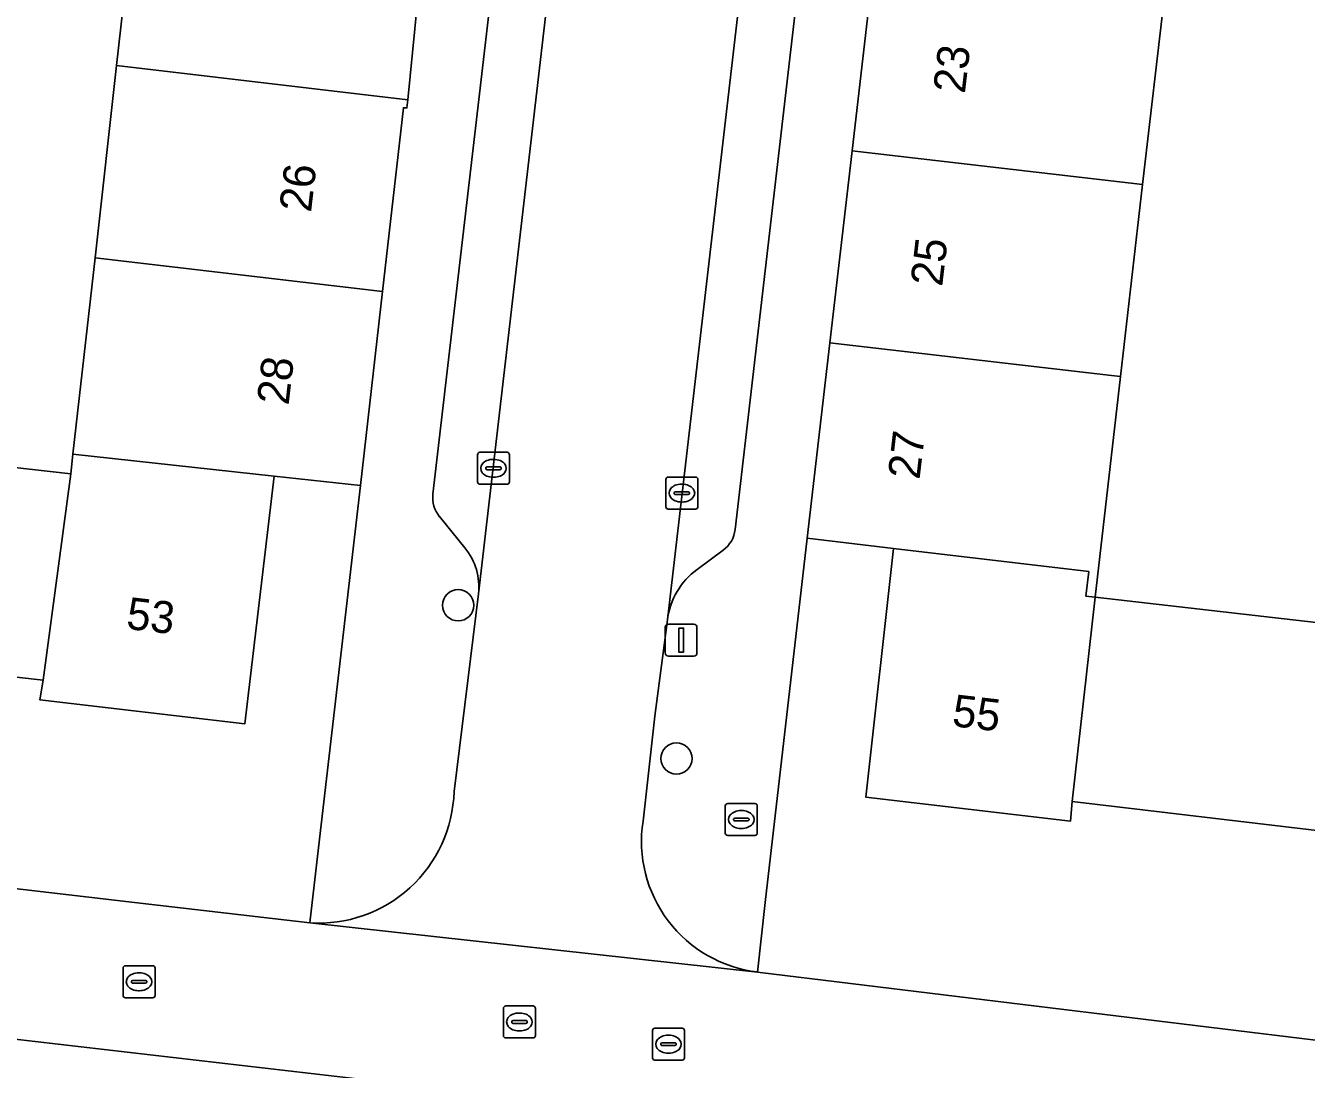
# Model space of a CAD drawing. Extents: x 161241 to 161758, y 384138 to 384885.
# Drawn here: x 161433.37 to 161473.44, y 384494.77 to 384527.43 of the extents above; entities that cross this region are included whole.
import ezdxf

# ---------------------------------------------------------------- set-up
doc = ezdxf.new("R2010")
doc.units = 0
for name, color, linetype in [('IMGEO_Boom', 7, 'Continuous'), ('IMGEO_Brandkraan', 7, 'Continuous'), ('IMGEO_Erf', 7, 'Continuous'), ('IMGEO_Kolk', 7, 'Continuous'), ('IMGEO_Lichtmast', 7, 'Continuous'), ('IMGEO_Pand', 7, 'Continuous'), ('IMGEO_Pand_nummerreeks', 7, 'Continuous'), ('IMGEO_Parkeervlak_open', 7, 'Continuous'), ('IMGEO_Rijbaan_lokaal_open', 7, 'Continuous'), ('IMGEO_Rioolput', 7, 'Continuous'), ('IMGEO_Voetpad_open', 7, 'Continuous')]:
    doc.layers.add(name, color=color, linetype=linetype)

msp = doc.modelspace()

# ---------------------------------------------------------------- linework, layer by layer
at = {"layer": 'IMGEO_Boom'}
for centre in [(161446.901, 384509.294), (161453.731, 384504.499)]:
    msp.add_circle(centre, 0.489, dxfattribs=at)
at = {"layer": 'IMGEO_Brandkraan'}
for p, q in [((161455.259, 384502.166), (161455.259, 384503.018)), ((161455.334, 384503.092), (161456.186, 384503.092)), ((161455.747, 384502.872), (161455.772, 384502.872)), ((161456.26, 384503.018), (161456.26, 384502.166)), ((161455.518, 384502.586), (161455.518, 384502.598)), ((161455.956, 384502.549), (161455.558, 384502.549)), ((161455.561, 384502.635), (161455.959, 384502.635)), ((161456.002, 384502.598), (161456.002, 384502.586)), ((161456.186, 384502.092), (161455.334, 384502.092)), ((161455.77, 384502.312), (161455.745, 384502.312))]:
    msp.add_line(p, q, dxfattribs=at)
for points in [[(161455.259, 384502.166), (161455.259, 384503.018)], [(161455.334, 384503.092), (161456.186, 384503.092)], [(161456.26, 384503.018), (161456.26, 384502.166)], [(161456.186, 384502.092), (161455.334, 384502.092)]]:
    msp.add_lwpolyline(points, dxfattribs=at)
for centre, radius, start, end in [((161455.336, 384503.016), 0.0765, 91.552, 178.448), ((161455.336, 384503.016), 0.0765, 91.552, 178.448), ((161456.184, 384503.016), 0.0765, 1.552, 88.448), ((161456.184, 384503.016), 0.0765, 1.552, 88.448), ((161455.558, 384502.595), 0.0403, 85.8775, 175.7526), ((161455.555, 384502.585), 0.0366, 178.938, 274.7102), ((161455.959, 384502.592), 0.043, 264.8664, 352.4533), ((161455.963, 384502.597), 0.0386, 1.7309, 96.639), ((161455.336, 384502.168), 0.0765, 181.552, 268.448), ((161455.336, 384502.168), 0.0765, 181.552, 268.448), ((161456.184, 384502.168), 0.0765, 271.552, 358.448), ((161456.184, 384502.168), 0.0765, 271.552, 358.448)]:
    msp.add_arc(centre, radius, start, end, dxfattribs=at)
for centre, major_axis, ratio, start_param, end_param in [((161455.746, 384502.592), (-0.387, 0.002), 0.722429, 4.712389, 7.853982), ((161455.771, 384502.592), (-0.39, 0.002), 0.717154, 1.570796, 4.712389)]:
    msp.add_ellipse(centre, major_axis=major_axis, ratio=ratio, start_param=start_param, end_param=end_param, dxfattribs=at)
at = {"layer": 'IMGEO_Erf'}
for points in [[(161363.697, 384528.581), (161363.009, 384522.448), (161362.9, 384521.481), (161371.708, 384520.492), (161371.808, 384521.386), (161377.931, 384520.699), (161383.926, 384520.026), (161389.92, 384519.353), (161395.914, 384518.68), (161401.908, 384518.007), (161407.903, 384517.334), (161413.897, 384516.661), (161419.892, 384515.989), (161426.097, 384515.292), (161425.996, 384514.397), (161434.78, 384513.411), (161434.849, 384514.022), (161435.538, 384520.166), (161436.213, 384526.177), (161436.887, 384532.189)], [(161469.007, 384528.458), (161468.317, 384522.455), (161467.626, 384516.45), (161466.833, 384509.551), (161475.383, 384508.568)], [(161430.603, 384500.72), (161436.769, 384500), (161442.259, 384499.359), (161442.333, 384500), (161443.841, 384513.042), (161441.142, 384513.335), (161440.226, 384505.59), (161433.816, 384506.335), (161433.916, 384506.947), (161425.107, 384507.945)], [(161474.911, 384502.113), (161466.108, 384503.152), (161466.063, 384502.544), (161459.651, 384503.294), (161460.525, 384511.068), (161457.818, 384511.391), (161456.511, 384500), (161456.261, 384497.821), (161473.721, 384495.685)]]:
    msp.add_lwpolyline(points, dxfattribs=at)
at = {"layer": 'IMGEO_Kolk'}
for p, q in [((161447.505, 384513.154), (161447.505, 384514.006)), ((161447.58, 384514.08), (161448.432, 384514.08)), ((161448.506, 384514.006), (161448.506, 384513.154)), ((161447.807, 384513.623), (161448.205, 384513.623)), ((161447.993, 384513.86), (161448.018, 384513.86)), ((161447.764, 384513.574), (161447.764, 384513.586)), ((161448.202, 384513.537), (161447.804, 384513.537)), ((161448.016, 384513.3), (161447.991, 384513.3)), ((161448.248, 384513.586), (161448.248, 384513.574)), ((161453.399, 384512.378), (161453.399, 384513.23)), ((161453.474, 384513.304), (161454.326, 384513.304)), ((161454.4, 384513.23), (161454.4, 384512.378)), ((161448.432, 384513.08), (161447.58, 384513.08)), ((161453.658, 384512.798), (161453.658, 384512.81)), ((161453.701, 384512.847), (161454.099, 384512.847)), ((161453.887, 384513.084), (161453.912, 384513.084)), ((161454.142, 384512.81), (161454.142, 384512.798)), ((161454.096, 384512.761), (161453.698, 384512.761)), ((161453.91, 384512.524), (161453.885, 384512.524)), ((161454.326, 384512.304), (161453.474, 384512.304)), ((161436.491, 384498.015), (161437.343, 384498.015)), ((161436.416, 384497.089), (161436.416, 384497.941)), ((161436.904, 384497.795), (161436.929, 384497.795)), ((161437.417, 384497.941), (161437.417, 384497.089)), ((161436.675, 384497.509), (161436.675, 384497.521)), ((161437.113, 384497.472), (161436.715, 384497.472)), ((161436.718, 384497.558), (161437.116, 384497.558)), ((161436.927, 384497.235), (161436.902, 384497.235)), ((161437.159, 384497.521), (161437.159, 384497.509)), ((161437.343, 384497.015), (161436.491, 384497.015)), ((161452.98, 384495.137), (161452.98, 384495.989)), ((161453.055, 384496.063), (161453.907, 384496.063)), ((161453.981, 384495.989), (161453.981, 384495.137)), ((161453.239, 384495.557), (161453.239, 384495.569)), ((161453.282, 384495.606), (161453.68, 384495.606)), ((161453.468, 384495.843), (161453.493, 384495.843)), ((161453.723, 384495.569), (161453.723, 384495.557)), ((161453.677, 384495.52), (161453.279, 384495.52)), ((161453.491, 384495.283), (161453.466, 384495.283)), ((161453.907, 384495.063), (161453.055, 384495.063))]:
    msp.add_line(p, q, dxfattribs=at)
for points in [[(161447.505, 384513.154), (161447.505, 384514.006)], [(161447.58, 384514.08), (161448.432, 384514.08)], [(161448.506, 384514.006), (161448.506, 384513.154)], [(161453.399, 384512.378), (161453.399, 384513.23)], [(161453.474, 384513.304), (161454.326, 384513.304)], [(161454.4, 384513.23), (161454.4, 384512.378)], [(161448.432, 384513.08), (161447.58, 384513.08)], [(161454.326, 384512.304), (161453.474, 384512.304)], [(161436.491, 384498.015), (161437.343, 384498.015)], [(161436.416, 384497.089), (161436.416, 384497.941)], [(161437.417, 384497.941), (161437.417, 384497.089)], [(161437.343, 384497.015), (161436.491, 384497.015)], [(161452.98, 384495.137), (161452.98, 384495.989)], [(161453.055, 384496.063), (161453.907, 384496.063)], [(161453.981, 384495.989), (161453.981, 384495.137)], [(161453.907, 384495.063), (161453.055, 384495.063)]]:
    msp.add_lwpolyline(points, dxfattribs=at)
for centre, radius, start, end in [((161447.582, 384514.004), 0.0765, 91.552, 178.448), ((161447.582, 384514.004), 0.0765, 91.552, 178.448), ((161448.43, 384514.004), 0.0765, 1.552, 88.448), ((161448.43, 384514.004), 0.0765, 1.552, 88.448), ((161447.804, 384513.583), 0.0403, 85.8775, 175.7526), ((161448.209, 384513.585), 0.0386, 1.7309, 96.639), ((161447.801, 384513.573), 0.0366, 178.938, 274.7102), ((161448.205, 384513.58), 0.043, 264.8664, 352.4533), ((161453.476, 384513.228), 0.0765, 91.552, 178.448), ((161453.476, 384513.228), 0.0765, 91.552, 178.448), ((161454.324, 384513.228), 0.0765, 1.552, 88.448), ((161454.324, 384513.228), 0.0765, 1.552, 88.448), ((161447.582, 384513.156), 0.0765, 181.552, 268.448), ((161447.582, 384513.156), 0.0765, 181.552, 268.448), ((161448.43, 384513.156), 0.0765, 271.552, 358.448), ((161448.43, 384513.156), 0.0765, 271.552, 358.448), ((161453.698, 384512.807), 0.0403, 85.8775, 175.7526), ((161453.695, 384512.797), 0.0366, 178.938, 274.7102), ((161454.099, 384512.804), 0.043, 264.8664, 352.4533), ((161454.103, 384512.809), 0.0386, 1.7309, 96.639), ((161453.476, 384512.38), 0.0765, 181.552, 268.448), ((161453.476, 384512.38), 0.0765, 181.552, 268.448), ((161454.324, 384512.38), 0.0765, 271.552, 358.448), ((161454.324, 384512.38), 0.0765, 271.552, 358.448), ((161436.493, 384497.939), 0.0765, 91.552, 178.448), ((161436.493, 384497.939), 0.0765, 91.552, 178.448), ((161437.341, 384497.939), 0.0765, 1.552, 88.448), ((161437.341, 384497.939), 0.0765, 1.552, 88.448), ((161436.715, 384497.518), 0.0403, 85.8775, 175.7526), ((161436.712, 384497.508), 0.0366, 178.938, 274.7102), ((161437.116, 384497.515), 0.043, 264.8664, 352.4533), ((161437.12, 384497.52), 0.0386, 1.7309, 96.639), ((161436.493, 384497.091), 0.0765, 181.552, 268.448), ((161436.493, 384497.091), 0.0765, 181.552, 268.448), ((161437.341, 384497.091), 0.0765, 271.552, 358.448), ((161437.341, 384497.091), 0.0765, 271.552, 358.448), ((161453.057, 384495.987), 0.0765, 91.552, 178.448), ((161453.057, 384495.987), 0.0765, 91.552, 178.448), ((161453.905, 384495.987), 0.0765, 1.552, 88.448), ((161453.905, 384495.987), 0.0765, 1.552, 88.448), ((161453.279, 384495.566), 0.0403, 85.8775, 175.7526), ((161453.276, 384495.556), 0.0366, 178.938, 274.7102), ((161453.68, 384495.563), 0.043, 264.8664, 352.4533), ((161453.684, 384495.568), 0.0386, 1.7309, 96.639), ((161453.057, 384495.139), 0.0765, 181.552, 268.448), ((161453.057, 384495.139), 0.0765, 181.552, 268.448), ((161453.905, 384495.139), 0.0765, 271.552, 358.448), ((161453.905, 384495.139), 0.0765, 271.552, 358.448)]:
    msp.add_arc(centre, radius, start, end, dxfattribs=at)
for centre, major_axis, ratio, start_param, end_param in [((161447.992, 384513.58), (-0.387, 0.002), 0.722429, 4.712389, 7.853982), ((161448.017, 384513.58), (-0.39, 0.002), 0.717154, 1.570796, 4.712389), ((161453.886, 384512.804), (-0.387, 0.002), 0.722429, 4.712389, 7.853982), ((161453.911, 384512.804), (-0.39, 0.002), 0.717154, 1.570796, 4.712389), ((161436.903, 384497.515), (-0.387, 0.002), 0.722429, 4.712389, 7.853982), ((161436.928, 384497.515), (-0.39, 0.002), 0.717154, 1.570796, 4.712389), ((161453.467, 384495.563), (-0.387, 0.002), 0.722429, 4.712389, 7.853982), ((161453.492, 384495.563), (-0.39, 0.002), 0.717154, 1.570796, 4.712389)]:
    msp.add_ellipse(centre, major_axis=major_axis, ratio=ratio, start_param=start_param, end_param=end_param, dxfattribs=at)
at = {"layer": 'IMGEO_Lichtmast'}
for p, q in [((161453.382, 384507.806), (161453.382, 384508.606)), ((161453.382, 384508.606), (161453.382, 384507.806)), ((161453.482, 384508.706), (161454.272, 384508.706)), ((161454.272, 384508.706), (161453.482, 384508.706)), ((161454.372, 384508.606), (161454.372, 384507.806)), ((161454.372, 384507.806), (161454.372, 384508.606)), ((161454.272, 384507.706), (161453.482, 384507.706)), ((161453.482, 384507.706), (161454.272, 384507.706))]:
    msp.add_line(p, q, dxfattribs=at)
msp.add_lwpolyline([(161453.802, 384508.581), (161453.952, 384508.581), (161453.952, 384507.831), (161453.802, 384507.831), (161453.802, 384508.581)], dxfattribs=at)
for centre, start, end in [((161453.482, 384508.606), 90, 180), ((161453.482, 384508.606), 90, 180), ((161454.272, 384508.606), 0, 90), ((161454.272, 384508.606), 360, 90), ((161453.482, 384507.806), 180, 270), ((161453.482, 384507.806), 180, 270), ((161454.272, 384507.806), 270, 0), ((161454.272, 384507.806), 270, 0)]:
    msp.add_arc(centre, 0.1, start, end, dxfattribs=at)
at = {"layer": 'IMGEO_Pand'}
for points in [[(161445.896, 384530.942), (161446.196, 384530.954), (161446.21, 384531.096), (161436.887, 384532.189), (161436.213, 384526.177), (161445.323, 384525.109)], [(161459.642, 384529.306), (161459.894, 384529.296), (161459.223, 384523.508), (161468.317, 384522.455), (161469.007, 384528.458), (161468.733, 384528.49), (161459.667, 384529.54)], [(161445.19, 384524.858), (161445.298, 384524.857), (161445.323, 384525.109), (161436.213, 384526.177), (161435.538, 384520.166), (161444.534, 384519.111)], [(161458.527, 384517.504), (161467.343, 384516.483), (161467.626, 384516.45), (161468.317, 384522.455), (161459.223, 384523.508)], [(161444.534, 384519.111), (161435.538, 384520.166), (161434.849, 384514.022), (161441.142, 384513.335), (161443.841, 384513.042)], [(161457.818, 384511.391), (161460.525, 384511.068), (161466.632, 384510.347), (161466.543, 384509.584), (161466.833, 384509.551), (161467.626, 384516.45), (161467.343, 384516.483), (161458.527, 384517.504)], [(161418.823, 384506.88), (161424.878, 384506.193), (161425.107, 384507.945), (161433.916, 384506.947), (161434.78, 384513.411), (161425.996, 384514.397), (161426.097, 384515.292), (161419.892, 384515.989)], [(161434.849, 384514.022), (161434.78, 384513.411), (161433.916, 384506.947), (161433.816, 384506.335), (161440.226, 384505.59), (161441.142, 384513.335)], [(161466.543, 384509.584), (161466.632, 384510.347), (161460.525, 384511.068), (161459.651, 384503.294), (161466.063, 384502.544), (161466.108, 384503.152), (161466.833, 384509.551)], [(161475.383, 384508.568), (161466.833, 384509.551), (161466.108, 384503.152), (161474.911, 384502.113), (161475.672, 384508.413), (161475.37, 384508.45)]]:
    msp.add_lwpolyline(points, close=True, dxfattribs=at)
at = {"layer": 'IMGEO_Parkeervlak_open'}
for points in [[(161447.539, 384509.648), (161451.359, 384542.556), (161451.881, 384547.095), (161450.128, 384547.299), (161449.597, 384542.748), (161446.111, 384512.773)], [(161455.567, 384511.666), (161459.568, 384546.2), (161457.814, 384546.404), (161453.447, 384508.842)], [(161446.316, 384512.067), (161447.113, 384511.087)], [(161454.376, 384510.418), (161455.191, 384511.018)]]:
    msp.add_lwpolyline(points, dxfattribs=at)
for centre, radius, start, end in [((161447.048, 384512.662), 0.944, 173.271, 219.1122), ((161454.644, 384511.769), 0.929, 306.0898, 353.6616), ((161445.6, 384509.857), 1.95, 353.861, 39.1206), ((161455.754, 384508.544), 2.326, 126.3295, 172.6346)]:
    msp.add_arc(centre, radius, start, end, dxfattribs=at)
at = {"layer": 'IMGEO_Rijbaan_lokaal_open'}
for points in [[(161452.684, 384502.539), (161453.058, 384505.828), (161453.447, 384508.842), (161457.814, 384546.404), (161451.881, 384547.095), (161451.359, 384542.556), (161447.539, 384509.648), (161446.771, 384503.468)], [(161513.174, 384491.028), (161506.677, 384491.817), (161500, 384492.603), (161498.849, 384492.738), (161473.721, 384495.685), (161456.261, 384497.821), (161442.259, 384499.359), (161436.769, 384500), (161430.603, 384500.72), (161430.519, 384500), (161430.062, 384496.065), (161448.776, 384493.891), (161500, 384487.889), (161510.654, 384486.641), (161513.81, 384486.25), (161514.621, 384486.15), (161520.975, 384485.363), (161528.385, 384500), (161539.084, 384521.135)], [(161442.259, 384499.359), (161456.261, 384497.821)]]:
    msp.add_lwpolyline(points, dxfattribs=at)
for centre, radius, start, end in [((161442.537, 384503.586), 4.236, 266.2382, 358.409), ((161456.753, 384501.909), 4.117, 171.1932, 263.1427)]:
    msp.add_arc(centre, radius, start, end, dxfattribs=at)
at = {"layer": 'IMGEO_Rioolput'}
for p, q in [((161448.392, 384496.758), (161449.244, 384496.758)), ((161448.317, 384495.832), (161448.317, 384496.684)), ((161448.805, 384496.538), (161448.83, 384496.538)), ((161449.318, 384496.684), (161449.318, 384495.832)), ((161448.576, 384496.252), (161448.576, 384496.264)), ((161449.014, 384496.215), (161448.616, 384496.215)), ((161448.619, 384496.301), (161449.017, 384496.301)), ((161448.828, 384495.978), (161448.803, 384495.978)), ((161449.06, 384496.264), (161449.06, 384496.252)), ((161449.244, 384495.758), (161448.392, 384495.758))]:
    msp.add_line(p, q, dxfattribs=at)
for points in [[(161448.392, 384496.758), (161449.244, 384496.758)], [(161448.317, 384495.832), (161448.317, 384496.684)], [(161449.318, 384496.684), (161449.318, 384495.832)], [(161449.244, 384495.758), (161448.392, 384495.758)]]:
    msp.add_lwpolyline(points, dxfattribs=at)
for centre, radius, start, end in [((161448.394, 384496.682), 0.0765, 91.552, 178.448), ((161448.394, 384496.682), 0.0765, 91.552, 178.448), ((161449.242, 384496.682), 0.0765, 1.552, 88.448), ((161449.242, 384496.682), 0.0765, 1.552, 88.448), ((161448.616, 384496.261), 0.0403, 85.8775, 175.7526), ((161448.613, 384496.251), 0.0366, 178.938, 274.7102), ((161449.017, 384496.258), 0.043, 264.8664, 352.4533), ((161449.021, 384496.263), 0.0386, 1.7309, 96.639), ((161448.394, 384495.834), 0.0765, 181.552, 268.448), ((161448.394, 384495.834), 0.0765, 181.552, 268.448), ((161449.242, 384495.834), 0.0765, 271.552, 358.448), ((161449.242, 384495.834), 0.0765, 271.552, 358.448)]:
    msp.add_arc(centre, radius, start, end, dxfattribs=at)
for centre, major_axis, ratio, start_param, end_param in [((161448.804, 384496.258), (-0.387, 0.002), 0.722429, 4.712389, 7.853982), ((161448.829, 384496.258), (-0.39, 0.002), 0.717154, 1.570796, 4.712389)]:
    msp.add_ellipse(centre, major_axis=major_axis, ratio=ratio, start_param=start_param, end_param=end_param, dxfattribs=at)
at = {"layer": 'IMGEO_Voetpad_open'}
for points in [[(161446.111, 384512.773), (161449.597, 384542.748), (161450.128, 384547.299), (161450.43, 384549.88), (161451.107, 384555.678)], [(161460.551, 384554.685), (161459.867, 384548.782), (161459.568, 384546.2), (161455.567, 384511.666)], [(161456.261, 384497.821), (161456.511, 384500), (161457.818, 384511.391), (161458.527, 384517.504), (161459.223, 384523.508), (161459.894, 384529.296), (161459.642, 384529.306), (161459.667, 384529.54), (161459.712, 384529.959), (161460.008, 384529.927), (161460.601, 384535.258), (161460.337, 384535.278), (161460.369, 384535.543), (161460.415, 384535.921), (161460.683, 384535.879), (161461.348, 384541.513)], [(161445.896, 384530.942), (161445.323, 384525.109), (161445.298, 384524.857), (161445.19, 384524.858), (161444.534, 384519.111), (161443.841, 384513.042), (161442.333, 384500), (161442.259, 384499.359)], [(161447.113, 384511.087), (161446.316, 384512.067)], [(161455.191, 384511.018), (161454.376, 384510.418)], [(161446.771, 384503.468), (161447.539, 384509.648)], [(161453.447, 384508.842), (161453.058, 384505.828), (161452.684, 384502.539)]]:
    msp.add_lwpolyline(points, dxfattribs=at)
msp.add_lwpolyline([(161430.062, 384496.065), (161427.321, 384496.383), (161396.178, 384500), (161357.097, 384504.581), (161354.376, 384504.9), (161340.82, 384506.489), (161340.647, 384506.515), (161340.403, 384504.377), (161341.704, 384504.225), (161377.935, 384500), (161395.453, 384497.957), (161401.111, 384497.3), (161421.466, 384494.929), (161433, 384493.585), (161437.975, 384493.006), (161442.515, 384492.47), (161448.511, 384491.779), (161454.323, 384491.094), (161500, 384485.79), (161510.344, 384484.589), (161510.654, 384486.641), (161500, 384487.889), (161448.776, 384493.891)], close=True, dxfattribs=at)
for centre, radius, start, end in [((161447.048, 384512.662), 0.944, 173.271, 219.1122), ((161454.644, 384511.769), 0.929, 306.0898, 353.6616), ((161445.6, 384509.857), 1.95, 353.861, 39.1206), ((161455.754, 384508.544), 2.326, 126.3295, 172.6346), ((161442.537, 384503.586), 4.236, 266.2382, 358.409), ((161456.753, 384501.909), 4.117, 171.1932, 263.1427)]:
    msp.add_arc(centre, radius, start, end, dxfattribs=at)

# ---------------------------------------------------------------- texts
at = {"layer": 'IMGEO_Pand_nummerreeks'}
for s, rotation, p in [('23', 83.3027, (161462.752, 384525.282)), ('26', 83.3656, (161442.295, 384521.565)), ('25', 83.3027, (161462.043, 384519.245)), ('28', 83.3656, (161441.593, 384515.533)), ('27', 83.3027, (161461.334, 384513.207)), ('53', 353.3706, (161436.491, 384508.561)), ('55', 353.3285, (161462.329, 384505.517))]:
    msp.add_text(s, height=1, rotation=rotation, dxfattribs=at).set_placement(p)

doc.saveas('drawing.dxf')
